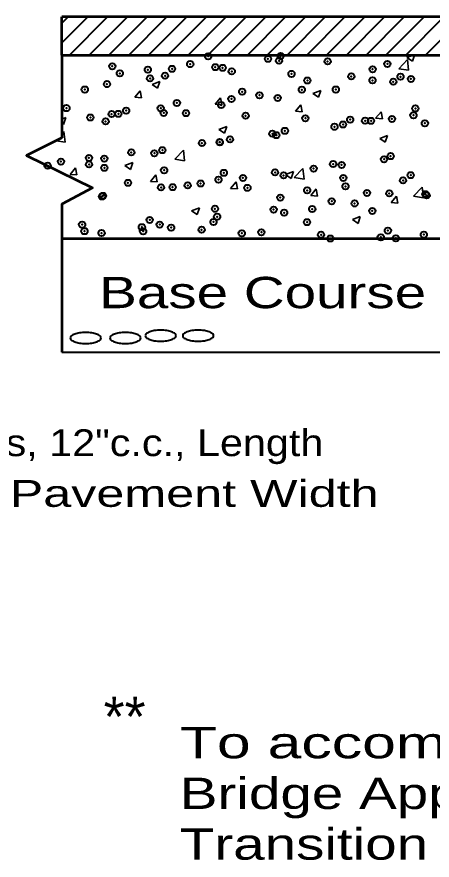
# Model space of a CAD drawing. Extents: x 36.4 to 71.7, y 0.5 to 22.5.
# Drawn here: x 53.788 to 55.644, y 6.336 to 10.106 of the extents above; entities that cross this region are included whole.
import ezdxf

# ---------------------------------------------------------------- set-up
doc = ezdxf.new("R2010")
doc.units = 0
doc.header["$LTSCALE"] = 0.056
doc.header["$PDMODE"] = 32
doc.header["$PDSIZE"] = 0.028
doc.layers.add('1', color=7, linetype='Continuous', lineweight=40)
doc.layers.add('3', color=7, linetype='Continuous', lineweight=13)

msp = doc.modelspace()

# ---------------------------------------------------------------- linework, layer by layer
at = {"layer": '1', "lineweight": 53}
for p, q in [((58.57958, 10.10608), (53.98842, 10.10608)), ((53.98842, 9.9355), (53.98842, 10.10608)), ((53.98842, 9.9355), (53.98842, 9.56492))]:
    msp.add_line(p, q, dxfattribs=at)
at = {"layer": '1'}
for p, q in [((53.98842, 9.98925), (54.10525, 10.10608)), ((53.98842, 10.07767), (54.01683, 10.10608)), ((54.023, 9.9355), (54.19358, 10.10608)), ((54.11142, 9.9355), (54.282, 10.10608)), ((54.19975, 9.9355), (54.37042, 10.10608)), ((54.28817, 9.9355), (54.45875, 10.10608)), ((54.37658, 9.9355), (54.54717, 10.10608)), ((54.46492, 9.9355), (54.63558, 10.10608)), ((54.55333, 9.9355), (54.72392, 10.10608)), ((54.64175, 9.9355), (54.81233, 10.10608)), ((54.73008, 9.9355), (54.90075, 10.10608)), ((54.8185, 9.9355), (54.98908, 10.10608)), ((54.90692, 9.9355), (55.0775, 10.10608)), ((54.99525, 9.9355), (55.16592, 10.10608)), ((55.08367, 9.9355), (55.25425, 10.10608)), ((55.17208, 9.9355), (55.34267, 10.10608)), ((55.26042, 9.9355), (55.43108, 10.10608)), ((55.34883, 9.9355), (55.51942, 10.10608)), ((55.43725, 9.9355), (55.60783, 10.10608)), ((55.52558, 9.9355), (55.69625, 10.10608)), ((55.614, 9.9355), (55.78458, 10.10608)), ((53.98842, 8.60725), (58.57958, 8.60725))]:
    msp.add_line(p, q, dxfattribs=at)
at = {"layer": '1', "lineweight": 35}
for p, q in [((55.53108, 9.92467), (55.55908, 9.9355)), ((55.53108, 9.92467), (55.55592, 9.90792)), ((55.55592, 9.90792), (55.56517, 9.9355)), ((55.49442, 9.87433), (55.53333, 9.91492)), ((55.53883, 9.86742), (55.53333, 9.91492)), ((55.49442, 9.87433), (55.53883, 9.86742)), ((54.39233, 9.8035), (54.42742, 9.81692)), ((54.39233, 9.8035), (54.41725, 9.78667)), ((54.41725, 9.78667), (54.42742, 9.81692)), ((54.3155, 9.74667), (54.33958, 9.77542)), ((54.34533, 9.744), (54.33958, 9.77542)), ((55.11092, 9.76342), (55.14592, 9.77692)), ((55.13583, 9.74667), (55.14592, 9.77683)), ((54.3155, 9.74667), (54.34533, 9.74408)), ((54.67408, 9.71533), (54.69817, 9.744)), ((54.704, 9.71267), (54.69825, 9.744)), ((55.11092, 9.76342), (55.13583, 9.74667)), ((54.67408, 9.71533), (54.704, 9.71267)), ((55.03275, 9.68392), (55.05683, 9.71267)), ((55.06258, 9.68125), (55.05683, 9.71267)), ((53.98842, 9.64842), (54.00725, 9.65567)), ((53.99717, 9.62542), (54.00725, 9.65567)), ((55.03275, 9.68392), (55.06258, 9.68133)), ((55.39133, 9.6525), (55.4155, 9.68125)), ((55.39133, 9.6525), (55.42125, 9.64992)), ((55.42125, 9.64992), (55.4155, 9.68125)), ((53.98842, 9.63133), (53.99717, 9.62542)), ((54.69083, 9.60217), (54.72583, 9.61558)), ((54.71567, 9.58542), (54.72583, 9.61558)), ((53.98842, 9.58258), (53.99875, 9.59342)), ((54.00425, 9.54592), (53.99875, 9.59342)), ((54.69083, 9.60217), (54.71567, 9.58542)), ((53.96317, 9.55225), (54.00425, 9.54592)), ((55.40942, 9.56217), (55.44442, 9.57558)), ((55.40942, 9.56217), (55.43425, 9.54533)), ((55.43425, 9.54533), (55.44442, 9.57558)), ((54.49342, 9.47008), (54.53233, 9.51067)), ((54.53792, 9.46317), (54.53242, 9.51058)), ((54.49342, 9.47008), (54.53792, 9.46317)), ((54.02625, 9.40192), (54.05033, 9.43067)), ((54.05608, 9.39933), (54.05033, 9.43067)), ((54.27075, 9.44092), (54.30575, 9.45433)), ((54.27075, 9.44092), (54.29558, 9.42417)), ((54.29558, 9.42408), (54.30575, 9.45433)), ((55.02708, 9.38725), (55.066, 9.42792)), ((55.0715, 9.38042), (55.066, 9.42783)), ((54.02625, 9.40192), (54.05608, 9.39933)), ((54.38483, 9.37058), (54.40892, 9.39933)), ((54.41475, 9.36792), (54.40892, 9.39925)), ((54.98925, 9.40083), (55.02425, 9.41433)), ((54.98925, 9.40083), (55.01417, 9.38408)), ((55.01417, 9.38408), (55.02433, 9.41425)), ((54.38483, 9.37058), (54.41475, 9.368)), ((54.7435, 9.33917), (54.76758, 9.36792)), ((54.77333, 9.33658), (54.76758, 9.36792)), ((55.02708, 9.38725), (55.0715, 9.38042)), ((54.7435, 9.33917), (54.77333, 9.33658)), ((55.10208, 9.30783), (55.12625, 9.33658)), ((55.132, 9.30517), (55.12625, 9.3365)), ((55.56067, 9.3045), (55.59958, 9.34508)), ((55.60517, 9.29758), (55.59958, 9.34508)), ((55.10208, 9.30783), (55.132, 9.30517)), ((55.46075, 9.27642), (55.48483, 9.30517)), ((55.46075, 9.27642), (55.49058, 9.27383)), ((55.49067, 9.27383), (55.48483, 9.30517)), ((55.56067, 9.3045), (55.60517, 9.29767)), ((54.56917, 9.23958), (54.60417, 9.253)), ((54.56917, 9.23958), (54.594, 9.22283)), ((54.59408, 9.22283), (54.60417, 9.253)), ((55.28775, 9.19958), (55.32275, 9.213)), ((55.28775, 9.19958), (55.31258, 9.18275)), ((55.31258, 9.18275), (55.32275, 9.213))]:
    msp.add_line(p, q, dxfattribs=at)
at = {"layer": '1', "lineweight": 53}
for points in [[(53.98842, 9.9355), (58.57958, 9.9355), (58.57958, 10.10608)], [(53.98842, 9.56492), (53.83075, 9.48583), (54.12633, 9.34117), (53.98842, 9.26875), (53.98842, 8.60725)], [(58.57958, 8.94833), (57.81108, 8.94833), (55.79142, 9.11375), (53.98842, 9.11375)]]:
    msp.add_lwpolyline(points, dxfattribs=at)
at = {"layer": '1'}
for centre, radius, start, end in [((54.03675, 8.6705), 0.01012, 130.84655, 180.07799), ((54.06467, 8.63833), 0.05269, 109.77026, 130.885), ((54.08292, 8.58583), 0.10826, 98.25297, 109.4918), ((54.09567, 8.50258), 0.19248, 90.02264, 98.43766), ((54.09558, 8.502), 0.19304, 81.57477, 89.98979), ((54.10825, 8.58625), 0.10785, 70.454, 81.69283), ((54.1265, 8.63833), 0.05269, 49.11499, 70.22974), ((54.15442, 8.67042), 0.01016, 0.43525, 49.6667), ((54.21408, 8.6705), 0.01012, 130.84655, 180.07799), ((54.242, 8.63833), 0.05269, 109.77026, 130.885), ((54.26025, 8.58583), 0.10826, 98.25297, 109.4918), ((54.273, 8.50258), 0.19248, 90.02264, 98.43766), ((54.27292, 8.502), 0.19304, 81.57477, 89.98979), ((54.28558, 8.58625), 0.10785, 70.454, 81.69283), ((54.30383, 8.63833), 0.05269, 49.11499, 70.22974), ((54.33175, 8.67042), 0.01016, 0.43525, 49.6667), ((54.37183, 8.68083), 0.01025, 180.19847, 229.42992), ((54.37175, 8.68075), 0.01016, 130.3333, 179.56474), ((54.39942, 8.713), 0.05258, 229.32889, 250.44364), ((54.39967, 8.64867), 0.05269, 109.77026, 130.885), ((54.41792, 8.59658), 0.10785, 98.30717, 109.546), ((54.43058, 8.51233), 0.19304, 90.0102, 98.42523), ((54.4305, 8.51292), 0.19248, 81.56233, 89.97736), ((54.44325, 8.59617), 0.10826, 70.5082, 81.74703), ((54.4615, 8.64867), 0.05269, 49.11499, 70.22974), ((54.46175, 8.713), 0.05258, 289.55636, 310.6711), ((54.48942, 8.68083), 0.01012, 359.922, 49.15345), ((54.48933, 8.68075), 0.01021, 311.07972, 0.31117), ((54.53933, 8.68083), 0.01025, 180.19847, 229.42992), ((54.53925, 8.68075), 0.01016, 130.3333, 179.56474), ((54.56692, 8.713), 0.05258, 229.32889, 250.44364), ((54.56717, 8.64867), 0.05269, 109.77026, 130.885), ((54.58542, 8.59658), 0.10785, 98.30717, 109.546), ((54.59808, 8.51233), 0.19304, 90.0102, 98.42523), ((54.598, 8.51292), 0.19248, 81.56233, 89.97736), ((54.61075, 8.59617), 0.10826, 70.5082, 81.74703), ((54.629, 8.64867), 0.05269, 49.11499, 70.22974), ((54.62925, 8.713), 0.05258, 289.55636, 310.6711), ((54.65692, 8.68083), 0.01012, 359.922, 49.15345), ((54.65683, 8.68075), 0.01021, 311.07972, 0.31117), ((54.03683, 8.67042), 0.01021, 179.68883, 228.92027), ((54.06442, 8.70267), 0.05258, 229.32889, 250.44364), ((54.08342, 8.75508), 0.10836, 250.28977, 261.5286), ((54.09567, 8.83833), 0.19248, 261.56233, 269.97736), ((54.09558, 8.83892), 0.19304, 270.0102, 278.42523), ((54.10783, 8.75467), 0.10795, 278.52638, 289.76521), ((54.12675, 8.70267), 0.05258, 289.55636, 310.6711), ((54.15433, 8.6705), 0.01025, 310.57008, 359.80152), ((54.21417, 8.67042), 0.01021, 179.68883, 228.92027), ((54.24175, 8.70267), 0.05258, 229.32889, 250.44364), ((54.26075, 8.75508), 0.10836, 250.28977, 261.5286), ((54.273, 8.83833), 0.19248, 261.56233, 269.97736), ((54.27292, 8.83892), 0.19304, 270.0102, 278.42523), ((54.28517, 8.75467), 0.10795, 278.52638, 289.76521), ((54.30408, 8.70267), 0.05258, 289.55636, 310.6711), ((54.33167, 8.6705), 0.01025, 310.57008, 359.80152), ((54.41833, 8.765), 0.10795, 250.23479, 261.47362), ((54.43058, 8.84925), 0.19304, 261.57477, 269.98979), ((54.4305, 8.84867), 0.19248, 270.02264, 278.43766), ((54.44275, 8.76542), 0.10836, 278.47139, 289.71023), ((54.58583, 8.765), 0.10795, 250.23479, 261.47362), ((54.59808, 8.84925), 0.19304, 261.57477, 269.98979), ((54.598, 8.84867), 0.19248, 270.02264, 278.43766), ((54.61025, 8.76542), 0.10836, 278.47139, 289.71023)]:
    msp.add_arc(centre, radius, start, end, dxfattribs=at)
for p in [(54.64308, 9.92967), (54.91, 9.91833), (54.95992, 9.91008), (54.9665, 9.93125), (55.17683, 9.90708), (54.21467, 9.885), (54.37333, 9.86992), (54.48158, 9.87375), (54.56275, 9.89483), (54.67492, 9.88125), (54.70733, 9.87808), (55.37792, 9.87158), (55.44375, 9.89583), (54.24817, 9.85342), (54.38333, 9.83117), (54.45058, 9.84292), (54.7485, 9.8625), (55.01542, 9.85117), (55.28233, 9.83992), (55.50242, 9.83867), (55.54917, 9.82867), (54.19092, 9.80542), (55.08633, 9.8215), (55.37725, 9.82217), (55.47025, 9.81633), (54.09175, 9.78117), (54.79475, 9.77142), (54.87217, 9.75567), (55.0615, 9.78058), (55.2135, 9.78117), (54.50317, 9.72142), (54.747, 9.73917), (54.95383, 9.74367), (54.00975, 9.69808), (54.27667, 9.68675), (54.43117, 9.69758), (54.4445, 9.67642), (54.54358, 9.6755), (54.70125, 9.71167), (55.56892, 9.69658), (54.11667, 9.65617), (54.18483, 9.63892), (54.21158, 9.67133), (54.24183, 9.67267), (54.8105, 9.66425), (55.07742, 9.65292), (55.27733, 9.6465), (55.34433, 9.64167), (55.37092, 9.64142), (55.46417, 9.64992), (55.56025, 9.66633), (55.20742, 9.61467), (55.24575, 9.625), (55.61125, 9.63042), (54.93, 9.58342), (54.94775, 9.57725), (54.98575, 9.5965), (54.61542, 9.542), (54.69408, 9.54642), (54.69517, 9.54517), (54.74058, 9.55842), (54.29967, 9.50042), (54.4025, 9.49633), (54.43842, 9.51), (53.98508, 9.459), (54.11033, 9.4755), (54.17875, 9.4725), (55.42875, 9.46917), (55.45808, 9.4835), (53.92617, 9.4405), (54.11092, 9.44633), (54.17933, 9.43125), (54.44617, 9.42), (55.11425, 9.42775), (55.20133, 9.44825), (55.23942, 9.44425), (54.68908, 9.37875), (54.71308, 9.40875), (54.79842, 9.38617), (54.94167, 9.41075), (54.98, 9.39742), (55.24692, 9.38617), (55.51383, 9.37492), (55.54825, 9.39825), (54.28475, 9.36408), (54.43233, 9.34358), (54.48392, 9.34475), (54.55167, 9.35283), (54.60908, 9.36125), (54.8185, 9.34158), (55.25667, 9.34817), (54.16817, 9.30317), (54.17267, 9.30608), (54.96508, 9.29817), (55.08542, 9.33025), (55.35233, 9.319), (55.452, 9.317), (55.613, 9.3135), (55.61925, 9.30775), (55.19525, 9.28183), (55.29725, 9.27192), (54.6735, 9.24808), (54.93558, 9.24433), (54.98267, 9.23058), (55.10783, 9.247), (55.3765, 9.23842), (54.38192, 9.198), (54.66692, 9.189), (54.683, 9.21233), (55.08483, 9.18833), (54.07983, 9.17708), (54.09025, 9.148), (54.34675, 9.16583), (54.35233, 9.14758), (54.42633, 9.17708), (54.4775, 9.16408), (54.61367, 9.15458), (55.44592, 9.15058), (54.16658, 9.13958), (54.79325, 9.13833), (54.88058, 9.14325), (55.1475, 9.132), (55.18917, 9.11533), (55.41433, 9.12075), (55.48142, 9.11633), (55.60658, 9.13283)]:
    msp.add_point(p, dxfattribs=at)

# ---------------------------------------------------------------- texts
at = {"layer": '3'}
for s, height, width, p in [('Base Course', 0.14, 1.35, (54.15592, 8.80367)), ('#5 Bars, 12"c.c., Length', 0.12, 1.15, (53.19417, 8.14225)), ('to be Pavement Width', 0.12, 1.4, (53.19417, 7.91558)), ('To accommodate separate pours for', 0.14, 1.45, (54.51625, 6.79142)), ('Bridge Approach Slab and Bridge', 0.14, 1.35, (54.51625, 6.56475)), ('Transition Pavement', 0.14, 1.35, (54.51625, 6.33808))]:
    msp.add_text(s, height=height, dxfattribs=dict(at, width=width)).set_placement(p)
msp.add_text('**', height=0.18, dxfattribs=at).set_placement((54.176, 6.8875))

doc.saveas('drawing.dxf')
